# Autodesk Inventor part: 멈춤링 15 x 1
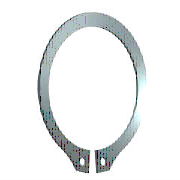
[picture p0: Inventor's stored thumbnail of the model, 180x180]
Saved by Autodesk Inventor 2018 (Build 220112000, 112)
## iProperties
IsCustomPart: 1
Created: 2012-02
Part Number: 멈춤링 15 x 1
Material: 강철, 연강
Description: 리테이닝 링(C형)
Document SubType Name: Modeling
Standard: KS B 1336
Designer: mduedu
Standards Organization: KS
Language: ko-KR
Size Designation: 15 x 1
Categories: <MemberInstance><Categories><Category DisplayName="샤프트 부품" InternalName="7f7aeb1f-a693-4053-b835-cee3144e0d98" Mnemonic="SHFT"><Category DisplayName="써클립" Inter
Density: 1 g/cm^3
Appearance: 파란색 - 벽 페인트 - 광택
Author: mduedu
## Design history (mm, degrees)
sketch "스케치1"
  geometry: L1 (-6, 0)-(6, 0) reference; L2 (0, 20.189)-(0, -80.536) reference; L3 (-48.09, 0)-(48.09, 0) reference; L4 (-0.425, -14.637)-(-0.425, -18.137); L5 (-0.425, -6.54)-(-0.425, -13.29); L6 (-2.795, 2.1)-(3.672, 2.1); L7 (0.425, -6.54)-(0.425, -13.29); L8 (0.425, -14.637)-(0.425, -18.137); C1 r 0.85 at (-1.7, -16.283); C2 r 0.85 at (1.7, -16.283); A1 r 7.15 centre (0, -7.5) between (0.425, -14.637) and (-0.425, -14.637); A2 r 9.075 centre (0, -6.975) between (4.291, -14.971) and (-4.291, -14.971); A3 r 10.646 centre (0, -7.5) between (-2.023, -17.952) and (-0.425, -18.137); A4 r 1.7 centre (-1.7, -16.283) between (-3.397, -16.376) and (-2.023, -17.952); A5 r 1.7 centre (-5.095, -16.469) between (-3.397, -16.376) and (-4.291, -14.971); A6 r 1.7 centre (5.095, -16.469) between (4.291, -14.971) and (3.397, -16.376); A7 r 1.7 centre (1.7, -16.283) between (2.023, -17.952) and (3.397, -16.376); A8 r 10.646 centre (0, -7.5) between (0.425, -18.137) and (2.023, -17.952)
  constraints: 16 point on circle, 12 end point, 10 centre point, 9 symmetric about line, 5 point on line, 4 tangent, 3 coincident, 2 horizontal, 1 perpendicular, 1 vertical, 5 other
  dimensions: "d0" = 14.3 diameter of A1 (= ND); "d1" = 3.5 distance of L4.end L4.start (= SRB2); "d6" = 0.425 distance between parallel lines of L2 L5 (= 0.25 x SD5); "d7" = 2.1 distance between parallel lines of L6 L3 (= SRB1); "d8" = 0.525 distance of A1.centre A2.centre (= 0.25 x SRB1); "d9" = 1.7 radius of A4 (= SD5); "d10" = 1.7 radius of A5 (= SD5); "d11" = 1.275 distance from line of L4 A4.centre (= 0.75 x SD5); "d12" = 1.7 diameter of C1 (= SD5); "d13" = 1.7 diameter of C2 (= SD5); "d14" = 7.5 distance from line of A1.centre L1 (= 0.5 x WD)
extrude "본체" new body sketch "스케치1" distance "d2" = 1 (= SD); taper "d3" = 0 deg
workaxis "Work Axis1"
workplane "Work Plane1"
body "Solid1"
other parameters: "WD" = 15 (= WDMIN) [user parameter; used in 1 equation term], "SD" = 1 [user parameter; used in 1 equation term], "SRB1" = 2.1 [user parameter; used in 2 equation terms], "ND" = 14.3 [user parameter; used in 1 equation term], "SRB2" = 3.5 [user parameter; used in 1 equation term], "SD5" = 1.7 [user parameter; used in 6 equation terms], "d15" = 0, "d16" = 0, "d17" = 0, "d41" = 0, "d42" = 0, "WDMIN" = 15 [user parameter; used in 1 equation term], "SD3" = 13.8 [user parameter], "WDMAX" = 16 [user parameter]
